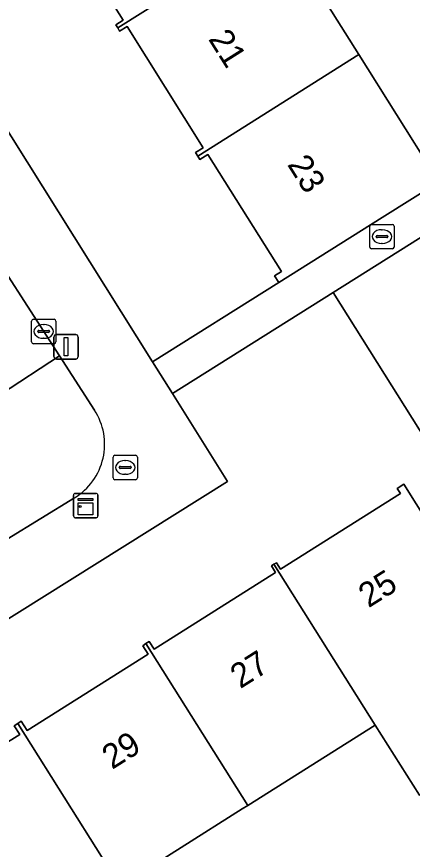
# Model space of a CAD drawing. Extents: x 160077 to 160948, y 386481 to 387498.
# Drawn here: x 160527.66 to 160543.85, y 386748.35 to 386782.41 of the extents above; entities that cross this region are included whole.
import ezdxf

# ---------------------------------------------------------------- set-up
doc = ezdxf.new("R2010")
doc.units = 0
for name, color, linetype in [('IMGEO_Erf', 7, 'Continuous'), ('IMGEO_Groenvoorziening', 7, 'Continuous'), ('IMGEO_Kast', 7, 'Continuous'), ('IMGEO_Kolk', 7, 'Continuous'), ('IMGEO_Lichtmast', 7, 'Continuous'), ('IMGEO_Pand', 7, 'Continuous'), ('IMGEO_Pand_nummerreeks', 7, 'Continuous'), ('IMGEO_Rioolput', 7, 'Continuous'), ('IMGEO_Voetpad_open', 7, 'Continuous')]:
    doc.layers.add(name, color=color, linetype=linetype)

msp = doc.modelspace()

# ---------------------------------------------------------------- linework, layer by layer
at = {"layer": 'IMGEO_Erf'}
for points in [[(160500, 386821.271), (160533.22, 386768.294), (160538.386, 386771.533), (160538.214, 386771.807), (160538.493, 386771.982), (160535.486, 386776.768), (160535.16, 386776.563), (160535.068, 386776.709), (160534.978, 386776.853), (160535.293, 386777.051), (160532.175, 386782.013), (160531.872, 386781.823), (160531.793, 386781.949), (160531.715, 386782.072), (160532.022, 386782.265), (160528.872, 386787.278)], [(160538.379, 386786.092), (160541.666, 386780.859), (160544.746, 386775.958), (160545.017, 386776.128), (160545.21, 386775.821), (160551.285, 386779.638), (160551.205, 386779.786), (160554.647, 386782.033), (160553.926, 386783.231), (160551.816, 386781.929), (160549.385, 386785.866)], [(160555.172, 386747.937), (160553.584, 386750.468), (160551.995, 386752.999), (160550.407, 386755.529), (160548.818, 386758.06), (160547.23, 386760.591), (160545.641, 386763.122), (160540.613, 386771.134), (160534.032, 386766.999), (160536.292, 386763.395), (160518.121, 386752.027), (160514.882, 386750), (160500, 386740.689)], [(160522.82, 386749.964), (160527.782, 386753.05), (160527.555, 386753.396), (160527.701, 386753.494), (160527.847, 386753.593), (160528.086, 386753.215), (160533.035, 386756.331), (160532.817, 386756.678), (160532.951, 386756.763), (160533.086, 386756.848), (160533.28, 386756.539), (160538.253, 386759.671), (160538.083, 386759.942), (160538.189, 386760.009), (160538.293, 386760.074), (160538.457, 386759.814), (160543.366, 386762.906), (160543.236, 386763.113), (160543.503, 386763.281), (160546.167, 386759.051)], [(160544.139, 386750.564), (160542.335, 386753.428), (160537.121, 386750.144), (160536.892, 386750), (160531.888, 386746.848)]]:
    msp.add_lwpolyline(points, dxfattribs=at)
at = {"layer": 'IMGEO_Groenvoorziening'}
msp.add_lwpolyline([(160529.409, 386768.538), (160525.866, 386774.021), (160521.015, 386771.06), (160524.568, 386765.372)], close=True, dxfattribs=at)
msp.add_lwpolyline([(160530.848, 386766.312), (160529.409, 386768.538), (160524.568, 386765.372), (160527.273, 386761.043), (160530.03, 386762.727)], dxfattribs=at)
msp.add_arc((160528.689, 386764.919), 2.57, 301.4624, 32.831, dxfattribs=at)
at = {"layer": 'IMGEO_Kast'}
for p, q in [((160529.984, 386761.986), (160529.984, 386762.827)), ((160529.984, 386762.827), (160529.984, 386761.986)), ((160530.059, 386762.911), (160530.9, 386762.911)), ((160530.9, 386762.911), (160530.059, 386762.911)), ((160530.984, 386762.836), (160530.984, 386761.995)), ((160530.984, 386761.995), (160530.984, 386762.836)), ((160530.909, 386761.911), (160530.068, 386761.911)), ((160530.068, 386761.911), (160530.909, 386761.911))]:
    msp.add_line(p, q, dxfattribs=at)
for points in [[(160530.179, 386762.701), (160530.779, 386762.701), (160530.779, 386762.616), (160530.179, 386762.616), (160530.179, 386762.701)], [(160530.179, 386762.526), (160530.779, 386762.526), (160530.779, 386762.037), (160530.179, 386762.037), (160530.179, 386762.526)]]:
    msp.add_lwpolyline(points, dxfattribs=at)
msp.add_circle((160530.263, 386762.375), 0.0377, dxfattribs=at)
for centre, start, end in [((160530.062, 386762.833), 92.4484, 184.2845), ((160530.062, 386762.833), 92.4484, 184.2845), ((160530.906, 386762.833), 2.4484, 94.2845), ((160530.906, 386762.833), 2.4484, 94.2845), ((160530.062, 386761.989), 182.4484, 274.2845), ((160530.062, 386761.989), 182.4484, 274.2845), ((160530.906, 386761.989), 272.4484, 4.2845), ((160530.906, 386761.989), 272.4484, 4.2845)]:
    msp.add_arc(centre, 0.0779, start, end, dxfattribs=at)
at = {"layer": 'IMGEO_Kolk'}
for p, q in [((160542.107, 386772.988), (160542.107, 386773.84)), ((160542.182, 386773.914), (160543.034, 386773.914)), ((160542.595, 386773.694), (160542.62, 386773.694)), ((160543.108, 386773.84), (160543.108, 386772.988)), ((160542.366, 386773.408), (160542.366, 386773.42)), ((160542.804, 386773.371), (160542.406, 386773.371)), ((160542.409, 386773.457), (160542.807, 386773.457)), ((160542.85, 386773.42), (160542.85, 386773.408)), ((160542.618, 386773.134), (160542.593, 386773.134)), ((160543.034, 386772.914), (160542.182, 386772.914)), ((160528.266, 386769.108), (160528.266, 386769.96)), ((160528.341, 386770.034), (160529.193, 386770.034)), ((160529.267, 386769.96), (160529.267, 386769.108)), ((160528.568, 386769.577), (160528.966, 386769.577)), ((160528.754, 386769.814), (160528.779, 386769.814)), ((160528.525, 386769.528), (160528.525, 386769.54)), ((160528.963, 386769.491), (160528.565, 386769.491)), ((160528.777, 386769.254), (160528.752, 386769.254)), ((160529.009, 386769.54), (160529.009, 386769.528)), ((160529.193, 386769.034), (160528.341, 386769.034))]:
    msp.add_line(p, q, dxfattribs=at)
for points in [[(160542.107, 386772.988), (160542.107, 386773.84)], [(160542.182, 386773.914), (160543.034, 386773.914)], [(160543.108, 386773.84), (160543.108, 386772.988)], [(160543.034, 386772.914), (160542.182, 386772.914)], [(160528.266, 386769.108), (160528.266, 386769.96)], [(160528.341, 386770.034), (160529.193, 386770.034)], [(160529.267, 386769.96), (160529.267, 386769.108)], [(160529.193, 386769.034), (160528.341, 386769.034)]]:
    msp.add_lwpolyline(points, dxfattribs=at)
for centre, radius, start, end in [((160542.184, 386773.838), 0.0765, 91.552, 178.448), ((160542.184, 386773.838), 0.0765, 91.552, 178.448), ((160543.032, 386773.838), 0.0765, 1.552, 88.448), ((160543.032, 386773.838), 0.0765, 1.552, 88.448), ((160542.406, 386773.417), 0.0403, 85.8775, 175.7526), ((160542.403, 386773.407), 0.0366, 178.938, 274.7102), ((160542.807, 386773.414), 0.043, 264.8664, 352.4533), ((160542.811, 386773.419), 0.0386, 1.7309, 96.639), ((160542.184, 386772.99), 0.0765, 181.552, 268.448), ((160542.184, 386772.99), 0.0765, 181.552, 268.448), ((160543.032, 386772.99), 0.0765, 271.552, 358.448), ((160543.032, 386772.99), 0.0765, 271.552, 358.448), ((160528.343, 386769.958), 0.0765, 91.552, 178.448), ((160528.343, 386769.958), 0.0765, 91.552, 178.448), ((160529.191, 386769.958), 0.0765, 1.552, 88.448), ((160529.191, 386769.958), 0.0765, 1.552, 88.448), ((160528.565, 386769.537), 0.0403, 85.8775, 175.7526), ((160528.97, 386769.539), 0.0386, 1.7309, 96.639), ((160528.562, 386769.527), 0.0366, 178.938, 274.7102), ((160528.966, 386769.534), 0.043, 264.8664, 352.4533), ((160528.343, 386769.11), 0.0765, 181.552, 268.448), ((160528.343, 386769.11), 0.0765, 181.552, 268.448), ((160529.191, 386769.11), 0.0765, 271.552, 358.448), ((160529.191, 386769.11), 0.0765, 271.552, 358.448)]:
    msp.add_arc(centre, radius, start, end, dxfattribs=at)
for centre, major_axis, ratio, start_param, end_param in [((160542.594, 386773.414), (-0.387, 0.002), 0.722429, 4.712389, 7.853982), ((160542.619, 386773.414), (-0.39, 0.002), 0.717154, 1.570796, 4.712389), ((160528.753, 386769.534), (-0.387, 0.002), 0.722429, 4.712389, 7.853982), ((160528.778, 386769.534), (-0.39, 0.002), 0.717154, 1.570796, 4.712389)]:
    msp.add_ellipse(centre, major_axis=major_axis, ratio=ratio, start_param=start_param, end_param=end_param, dxfattribs=at)
at = {"layer": 'IMGEO_Lichtmast'}
for p, q in [((160529.184, 386768.506), (160529.184, 386769.306)), ((160529.184, 386769.306), (160529.184, 386768.506)), ((160529.284, 386769.406), (160530.074, 386769.406)), ((160530.074, 386769.406), (160529.284, 386769.406)), ((160530.174, 386769.306), (160530.174, 386768.506)), ((160530.174, 386768.506), (160530.174, 386769.306)), ((160530.074, 386768.406), (160529.284, 386768.406)), ((160529.284, 386768.406), (160530.074, 386768.406))]:
    msp.add_line(p, q, dxfattribs=at)
msp.add_lwpolyline([(160529.604, 386769.281), (160529.754, 386769.281), (160529.754, 386768.531), (160529.604, 386768.531), (160529.604, 386769.281)], dxfattribs=at)
for centre, start, end in [((160529.284, 386769.306), 90, 180), ((160529.284, 386769.306), 90, 180), ((160530.074, 386769.306), 0, 90), ((160530.074, 386769.306), 360, 90), ((160529.284, 386768.506), 180, 270), ((160529.284, 386768.506), 180, 270), ((160530.074, 386768.506), 270, 0), ((160530.074, 386768.506), 270, 0)]:
    msp.add_arc(centre, 0.1, start, end, dxfattribs=at)
at = {"layer": 'IMGEO_Pand'}
for points in [[(160528.45, 386787.178), (160528.524, 386787.059), (160528.872, 386787.278), (160532.022, 386782.265), (160531.715, 386782.072), (160531.793, 386781.949), (160538.379, 386786.092), (160535.077, 386791.347)], [(160541.666, 386780.859), (160538.379, 386786.092), (160531.793, 386781.949), (160531.872, 386781.823), (160532.175, 386782.013), (160535.293, 386777.051), (160534.978, 386776.853), (160535.068, 386776.709)], [(160535.068, 386776.709), (160535.16, 386776.563), (160535.486, 386776.768), (160538.493, 386771.982), (160538.214, 386771.807), (160538.386, 386771.533), (160542.62, 386774.194), (160545.21, 386775.821), (160545.017, 386776.128), (160544.746, 386775.958), (160541.666, 386780.859)], [(160545.641, 386763.122), (160550.687, 386766.289), (160554.529, 386768.7), (160552.703, 386771.609), (160549.5, 386776.712), (160540.613, 386771.134)], [(160546.167, 386759.051), (160543.503, 386763.281), (160543.236, 386763.113), (160543.366, 386762.906), (160538.457, 386759.814), (160538.293, 386760.074), (160538.189, 386760.009), (160542.335, 386753.428), (160544.139, 386750.564), (160549.418, 386753.889), (160547.802, 386756.455)], [(160537.121, 386750.144), (160542.335, 386753.428), (160538.189, 386760.009), (160538.083, 386759.942), (160538.253, 386759.671), (160533.28, 386756.539), (160533.086, 386756.848), (160532.951, 386756.763)], [(160529.902, 386750), (160531.888, 386746.848), (160536.892, 386750), (160537.121, 386750.144), (160532.951, 386756.763), (160532.817, 386756.678), (160533.035, 386756.331), (160528.086, 386753.215), (160527.847, 386753.593), (160527.701, 386753.494)], [(160529.902, 386750), (160527.701, 386753.494), (160527.555, 386753.396), (160527.782, 386753.05), (160522.82, 386749.964), (160522.623, 386750.276), (160522.52, 386750.211), (160522.652, 386750), (160526.697, 386743.579), (160528.502, 386740.714), (160533.568, 386743.904), (160531.764, 386746.77), (160531.888, 386746.848)]]:
    msp.add_lwpolyline(points, close=True, dxfattribs=at)
at = {"layer": 'IMGEO_Rioolput'}
for p, q in [((160531.676, 386764.47), (160532.528, 386764.47)), ((160531.601, 386763.544), (160531.601, 386764.396)), ((160532.089, 386764.25), (160532.114, 386764.25)), ((160532.602, 386764.396), (160532.602, 386763.544)), ((160531.86, 386763.964), (160531.86, 386763.976)), ((160532.298, 386763.927), (160531.9, 386763.927)), ((160531.903, 386764.013), (160532.301, 386764.013)), ((160532.344, 386763.976), (160532.344, 386763.964)), ((160532.528, 386763.47), (160531.676, 386763.47)), ((160532.112, 386763.69), (160532.087, 386763.69))]:
    msp.add_line(p, q, dxfattribs=at)
for points in [[(160531.676, 386764.47), (160532.528, 386764.47)], [(160531.601, 386763.544), (160531.601, 386764.396)], [(160532.602, 386764.396), (160532.602, 386763.544)], [(160532.528, 386763.47), (160531.676, 386763.47)]]:
    msp.add_lwpolyline(points, dxfattribs=at)
for centre, radius, start, end in [((160531.678, 386764.394), 0.0765, 91.552, 178.448), ((160531.678, 386764.394), 0.0765, 91.552, 178.448), ((160532.526, 386764.394), 0.0765, 1.552, 88.448), ((160532.526, 386764.394), 0.0765, 1.552, 88.448), ((160531.9, 386763.973), 0.0403, 85.8775, 175.7526), ((160531.897, 386763.963), 0.0366, 178.938, 274.7102), ((160532.301, 386763.97), 0.043, 264.8664, 352.4533), ((160532.305, 386763.975), 0.0386, 1.7309, 96.639), ((160531.678, 386763.546), 0.0765, 181.552, 268.448), ((160531.678, 386763.546), 0.0765, 181.552, 268.448), ((160532.526, 386763.546), 0.0765, 271.552, 358.448), ((160532.526, 386763.546), 0.0765, 271.552, 358.448)]:
    msp.add_arc(centre, radius, start, end, dxfattribs=at)
for centre, major_axis, ratio, start_param, end_param in [((160532.088, 386763.97), (-0.387, 0.002), 0.722429, 4.712389, 7.853982), ((160532.113, 386763.97), (-0.39, 0.002), 0.717154, 1.570796, 4.712389)]:
    msp.add_ellipse(centre, major_axis=major_axis, ratio=ratio, start_param=start_param, end_param=end_param, dxfattribs=at)
at = {"layer": 'IMGEO_Voetpad_open'}
for points in [[(160487.431, 386835.412), (160496.638, 386820.704), (160500, 386815.333), (160500.779, 386814.089), (160501.675, 386812.637), (160511.177, 386797.531), (160512.129, 386796.086), (160525.003, 386775.498), (160525.866, 386774.021), (160529.409, 386768.538), (160530.848, 386766.312)], [(160473.964, 386804.652), (160500, 386763.239), (160504.545, 386756.01), (160505.586, 386754.336), (160508.266, 386750), (160508.689, 386749.315), (160500, 386743.867), (160497.159, 386742.086), (160491.592, 386738.604), (160490.538, 386737.945), (160479.992, 386731.209), (160477.966, 386729.906), (160479.334, 386727.742), (160481.483, 386729.137), (160498.1, 386739.5), (160500, 386740.689), (160514.882, 386750), (160518.121, 386752.027), (160536.292, 386763.395), (160534.032, 386766.999), (160533.223, 386768.289), (160533.22, 386768.294), (160500, 386821.271)], [(160530.03, 386762.727), (160527.273, 386761.043)]]:
    msp.add_lwpolyline(points, dxfattribs=at)
msp.add_lwpolyline([(160540.613, 386771.134), (160549.5, 386776.712), (160552.016, 386778.291), (160551.285, 386779.638), (160545.21, 386775.821), (160542.62, 386774.194), (160538.386, 386771.533), (160533.22, 386768.294), (160533.223, 386768.289), (160534.032, 386766.999)], close=True, dxfattribs=at)
msp.add_arc((160528.689, 386764.919), 2.57, 301.4624, 32.831, dxfattribs=at)

# ---------------------------------------------------------------- texts
at = {"layer": 'IMGEO_Pand_nummerreeks'}
for s, rotation, p in [('21', 302.1919, (160535.48, 386781.496)), ('23', 302.1919, (160538.712, 386776.364)), ('25', 32.2117, (160542.058, 386758.206)), ('27', 32.2101, (160536.81, 386754.9)), ('29', 32.2101, (160531.563, 386751.594))]:
    msp.add_text(s, height=1, rotation=rotation, dxfattribs=at).set_placement(p)

doc.saveas('drawing.dxf')
